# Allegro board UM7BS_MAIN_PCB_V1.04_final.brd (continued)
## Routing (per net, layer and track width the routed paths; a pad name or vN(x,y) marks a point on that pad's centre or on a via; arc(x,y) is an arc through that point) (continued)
M_A_DQ7: length 54.6
  TOP w0.102: v1(189.5,78.42) 188.48,77.4 188.48,75.82 188.25,75.58 188.25,75.26 188.33,75.18 188.33,74.92 188.04,74.62 U1.AP51
  TOP w0.127: CN1.18 218.42,96.25 v1(217.82,95.65)
  BOTTOM w0.127: v1(217.82,95.65) 217.01,95.65 216.63,95.26 216.63,93.59 217.31,92.9 217.31,89.89 217.15,89.73 216.91,89.73 216.74,89.89 216.74,92.26 216.61,92.39 216.42,92.39 216.29,92.26 216.29,89.99 216.15,89.85 212.82,89.85 212.62,89.65 212.62,86.93 211.73,86.04 194.9,86.04 191.49,82.63 191.49,81.5 189.5,79.51 v1(189.5,78.42)
M_A_DQ8: length 48.8
  TOP w0.114: v1(188.52,72.9) 188.35,73.07 U1.AP48
  TOP w0.127: v1(217.06,94.45) 217.66,95.05 CN1.22
  LAY4 w0.127: v1(217.06,94.45) 217.06,94.93 215.66,96.33 210.08,96.33 203.47,89.73 198.01,89.73 186.78,78.5 186.78,75.43 187.37,74.84 187.37,73.95 188.42,72.9 v1(188.52,72.9)
M_A_DQ9: length 50.5
  TOP w0.102: U1.AT47 v1(189.51,72.36)
  TOP w0.127: CN1.23 v1(213.25,94.75)
  LAY4 w0.102: 188.61,74.95 188.61,74.74 188.87,74.49 188.87,73.73 188.99,73.6 188.99,73.32 189.51,72.8 v1(189.51,72.36)
  LAY4 w0.127: 188.61,74.95 188.61,79.06 198.01,88.46 203.6,88.46 208.3,93.16 209.36,93.16 209.57,93.36 209.57,94.53 209.72,94.68 209.93,94.68 210.08,94.53 210.08,93.31 210.22,93.16 210.43,93.16 210.58,93.31 210.58,94.91 210.73,95.06 210.94,95.06 211.09,94.91 211.09,93.31 211.24,93.16 211.45,93.16 211.6,93.31 211.6,94.9 211.76,95.06 211.99,95.06 212.15,94.9 212.15,93.28 212.28,93.16 212.53,93.16 212.66,93.28 212.66,94.54 212.86,94.75 v1(213.25,94.75)
M_A_DQ10: length 44.6
  TOP w0.102: v1(191.53,72.71) 191.17,73.07 U1.AY48
  TOP w0.127: CN1.33 214.34,91.75 v1(215.54,90.55)
  LAY4 w0.102: v1(191.53,72.71) 191.91,73.09 191.91,74.61
  LAY4 w0.127: 191.91,74.61 191.91,74.87 192.65,75.61 192.65,78.53 195.09,80.96 202.2,80.96 209.06,87.82 212.39,87.82 212.52,87.7 212.52,87.19 212.65,87.06 212.9,87.06 213.03,87.19 213.03,87.7 213.15,87.82 213.41,87.82 213.54,87.7 213.54,87.19 213.66,87.06 213.92,87.06 214.04,87.19 214.04,87.7 214.17,87.82 214.42,87.82 214.55,87.7 214.55,87.19 214.68,87.06 214.93,87.06 215.06,87.19 215.06,87.7 215.19,87.82 215.41,87.82 215.92,88.33 215.92,90.17 v1(215.54,90.55)
M_A_DQ11: length 44.5
  TOP w0.102: v1(190.52,73.98) 190.28,73.74 U1.AV50
  TOP w0.127: CN1.34 218.42,91.45 v1(217.82,92.05)
  LAY4 w0.102: 190.77,75.38 190.52,75.12 v1(190.52,73.98)
  LAY4 w0.127: 190.77,75.38 191.03,75.63 191.03,79.06 196.11,84.14 200.45,84.14 200.58,84.01 200.58,83.12 200.71,83 200.96,83 201.09,83.12 201.09,84.01 201.21,84.14 201.47,84.14 201.59,84.01 201.59,83.12 201.72,83 201.98,83 202.1,83.12 202.1,84.01 202.23,84.14 202.58,84.14 209.82,91.38 217.16,91.38 v1(217.82,92.05)
M_A_DQ12: length 49.8
  TOP w0.114: v1(188.51,72.28) 188.11,72.28 U1.AP47
  TOP w0.127: CN1.24 v1(218.58,94.45)
  LAY4 w0.127: v1(188.51,72.28) 187.09,73.7 187.09,74.36 186.4,75.05 186.4,78.75 197.81,90.16 203.27,90.16 209.82,96.71 215.82,96.71 217.63,94.9 218.13,94.9 v1(218.58,94.45)
M_A_DQ13: length 48.2
  TOP w0.102: v1(189.49,73.6) 189.35,73.74 U1.AT50
  TOP w0.127: v1(214.77,94.75) 214.17,95.35 CN1.21
  LAY4 w0.102: 188.99,75 188.99,74.74 189.12,74.61 189.12,73.97 v1(189.49,73.6)
  LAY4 w0.127: v1(214.77,94.75) 215.84,94.75 216.04,94.54 216.04,93.33 215.87,93.16 215.62,93.16 215.44,93.33 215.44,94.05 215.32,94.17 215.06,94.17 214.94,94.05 214.94,93.43 214.79,93.28 214.58,93.28 214.43,93.43 214.43,94.15 214.28,94.3 214.07,94.3 213.92,94.15 213.92,93.47 213.79,93.35 213.31,93.35 212.66,92.7 208.47,92.7 203.85,88.08 198.19,88.08 188.99,78.88 188.99,75
M_A_DQ14: length 46.5
  TOP w0.102: v1(191.53,73.34) 191.13,73.74 U1.AY50
  TOP w0.127: v1(214.01,90.55) 213.41,91.15 CN1.35
  LAY4 w0.102: v1(191.53,73.34) 191.15,73.73 191.15,74.61 191.66,75.12
  LAY4 w0.127: v1(214.01,90.55) 214.01,90.18 213.81,89.98 212.81,89.98 212.6,89.78 212.6,88.33 212.48,88.2 212.22,88.2 212.1,88.33 212.1,90.47 211.95,90.62 211.74,90.62 211.59,90.47 211.59,88.33 211.46,88.2 211.21,88.2 211.08,88.33 211.08,90.31 210.9,90.49 210.64,90.49 210.46,90.31 210.46,88.46 210.33,88.33 210.06,88.33 209.94,88.46 209.94,88.82 209.79,88.97 209.58,88.97 209.43,88.82 209.43,88.46 209.3,88.33 208.68,88.33 201.85,81.5 194.99,81.5 192.27,78.78 192.27,75.73 191.66,75.12
M_A_DQ15: length 49.3
  TOP w0.102: v1(190.52,71.95) 190.22,71.65 U1.AV45
  TOP w0.127: CN1.36 v1(218.58,90.85)
  LAY4 w0.102: 191.15,75.12 190.9,74.87 190.9,72.33 v1(190.52,71.95)
  LAY4 w0.127: v1(218.58,90.85) 217.11,90.85 216.96,91 210.58,91 201.95,82.36 200.24,82.36 200.11,82.49 200.11,83.28 199.96,83.43 199.75,83.43 199.61,83.28 199.61,82.49 199.48,82.36 199.22,82.36 199.1,82.49 199.1,83.38 198.97,83.5 198.72,83.5 198.59,83.38 198.59,82.49 198.46,82.36 198.21,82.36 198.08,82.49 198.08,83.38 197.95,83.5 197.7,83.5 197.57,83.38 197.57,82.49 197.45,82.36 197.19,82.36 197.07,82.49 197.07,83.38 196.94,83.5 196.68,83.5 196.56,83.38 196.56,82.49 196.43,82.36 195.09,82.36 191.41,78.68 191.41,75.38 191.15,75.12
M_A_DQ16: length 51.4
  TOP w0.114: v1(188.49,68.52) 188.88,68.91 U1.AT40
  TOP w0.127: v1(218.58,89.05) CN1.42
  LAY3 w0.102: 186.71,74.74 186.96,74.49 186.96,70.04 v1(188.49,68.52)
  LAY3 w0.127: 186.71,74.74 186.58,74.87 186.58,78.55 196.99,88.97 208.3,88.97 210.53,91.2 217.08,91.2 218.58,89.69 v1(218.58,89.05)
M_A_DQ17: length 51.3
  TOP w0.102: U1.AP42 188.36,70.23 v1(188.51,70.37)
  TOP w0.127: CN1.41 213.22,89.35 v1(213.25,89.32)
  LAY3 w0.102: 188.1,75.5 187.9,75.3 187.9,70.98 v1(188.51,70.37)
  LAY3 w0.127: v1(213.25,89.32) 213.22,89.35 211.85,89.35 209.06,86.55 208.81,86.55 208.68,86.68 208.68,87.31 208.55,87.44 208.3,87.44 208.17,87.31 208.17,86.68 208.04,86.55 207.79,86.55 207.66,86.68 207.66,87.31 207.54,87.44 207.28,87.44 207.16,87.31 207.16,86.68 207.03,86.55 206.77,86.55 206.65,86.68 206.65,87.31 206.52,87.44 206.27,87.44 206.14,87.31 206.14,86.68 206.01,86.55 205.76,86.55 205.63,86.68 205.63,87.31 205.5,87.44 205.25,87.44 205.12,87.31 205.12,86.68 205,86.55 204.74,86.55 204.62,86.68 204.62,87.31 204.49,87.44 204.23,87.44 204.11,87.31 204.11,86.68 203.98,86.55 203.73,86.55 203.6,86.68 203.6,87.31 203.47,87.44 203.22,87.44 203.09,87.31 203.09,86.68 202.96,86.55 202.71,86.55 202.58,86.68 202.58,87.31 202.46,87.44 202.2,87.44 202.08,87.31 202.08,86.68 201.95,86.55 201.69,86.55 201.57,86.68 201.57,87.04 201.42,87.19 201.21,87.19 201.06,87.04 201.06,86.68 200.93,86.55 196.36,86.55 188.37,78.56 188.37,75.77 188.1,75.5
M_A_DQ18: length 45.1
  TOP w0.114: U1.AT38 188.93,67.94 v1(189.5,68.52)
  TOP w0.127: CN1.51 v1(213.25,86.35)
  LAY3 w0.102: 190.47,74.81 190.14,74.47 190.14,70.93 190.01,70.8 190.01,69.03 v1(189.5,68.52)
  LAY3 w0.127: v1(213.25,86.35) 213.46,86.35 213.63,86.17 213.63,85.79 213.5,85.66 211.47,85.66 209.95,84.14 209.95,82.23 209.82,82.11 209.22,82.11 209.1,82.23 209.1,82.74 208.97,82.87 208.72,82.87 208.59,82.74 208.59,82.23 208.46,82.11 208.21,82.11 208.08,82.23 208.08,82.74 207.95,82.87 207.7,82.87 207.57,82.74 207.57,82.23 207.45,82.11 207.19,82.11 207.06,82.23 207.06,82.74 206.94,82.87 206.68,82.87 206.56,82.74 206.56,82.23 206.43,82.11 206.18,82.11 206.05,82.23 206.05,82.74 205.92,82.87 205.67,82.87 205.54,82.74 205.54,82.23 205.41,82.11 195.22,82.11 191.25,78.15 191.25,75.59 190.47,74.81
M_A_DQ19: length 48.5
  TOP w0.102: U1.AP40 188.14,68.8 v1(188.49,69.15)
  TOP w0.127: CN1.40 v1(217.82,89.65)
  LAY3 w0.102: v1(188.49,69.15) 187.22,70.42 187.22,74.87 187.09,75
  LAY3 w0.127: v1(217.82,89.65) 217.35,90.12 210.55,90.12 208.69,88.25 196.92,88.25 186.96,78.3 186.96,75.12 187.09,75
M_A_DQ20: length 51.6
  TOP w0.114: U1.AT44 189.31,70.94 v1(189.51,71.13)
  TOP w0.127: CN1.50 v1(218.58,86.65)
  LAY3 w0.102: v1(189.51,71.13) 189.93,71.56 189.93,74.82 190.27,75.16
  LAY3 w0.127: 190.27,75.16 190.87,75.76 190.87,78.4 195.72,83.25 196.23,83.25 196.35,83.12 196.35,82.62 196.48,82.49 196.74,82.49 196.86,82.62 196.86,83.12 196.99,83.25 197.24,83.25 197.37,83.12 197.37,82.62 197.5,82.49 197.75,82.49 197.88,82.62 197.88,83.12 198.01,83.25 198.26,83.25 198.39,83.12 198.39,82.62 198.51,82.49 198.77,82.49 198.89,82.62 198.89,83.12 199.02,83.25 199.28,83.25 199.4,83.12 199.4,82.62 199.53,82.49 199.78,82.49 199.91,82.62 199.91,83.12 200.04,83.25 200.29,83.25 200.42,83.12 200.42,82.62 200.55,82.49 200.8,82.49 200.93,82.62 200.93,83.12 201.05,83.25 201.31,83.25 201.43,83.12 201.43,82.62 201.56,82.49 201.82,82.49 201.94,82.62 201.94,83.12 202.07,83.25 202.32,83.25 202.45,83.12 202.45,82.62 202.58,82.49 202.83,82.49 202.96,82.62 202.96,83.12 203.09,83.25 203.34,83.25 203.47,83.12 203.47,82.62 203.59,82.49 203.85,82.49 203.97,82.62 203.97,83.12 204.1,83.25 204.36,83.25 204.48,83.12 204.48,82.89 204.63,82.74 204.84,82.74 204.99,82.89 204.99,83.12 205.12,83.25 208.42,83.25 211.98,86.81 216.77,86.81 216.93,86.65 v1(218.58,86.65)
M_A_DQ21: length 49.9
  TOP w0.114: v1(190.39,69.92) 189.99,69.52 U1.AV41
  TOP w0.127: CN1.52 218.42,86.05 v1(217.82,85.45)
  LAY3 w0.102: 191.44,74.68 191.15,74.39 191.15,71.06 190.77,70.68 190.77,70.29 190.39,69.92 v1(190.39,69.92)
  LAY3 w0.127: v1(217.82,85.45) 217.08,85.45 216.96,85.32 216.96,82.76 216.81,82.62 216.6,82.62 216.45,82.76 216.45,85.22 216.26,85.41 215.98,85.41 215.79,85.22 215.79,82.8 215.6,82.62 215.34,82.62 215.16,82.8 215.16,83.94 214.95,84.14 214.72,84.14 214.52,83.94 214.52,82.23 213.63,81.35 195.85,81.35 192.65,78.15 192.65,75.88 191.44,74.68
M_A_DQ22: length 47.5
  TOP w0.102: v1(188.49,69.79) 188.21,69.51 U1.AP41
  TOP w0.127: CN1.39 214.15,89.95 v1(214.77,89.32)
  LAY3 w0.102: v1(188.49,69.79) 187.6,70.68 187.6,75.12 187.47,75.25
  LAY3 w0.127: v1(214.77,89.32) 214.35,89.74 211.1,89.74 209.19,87.82 200.75,87.82 200.62,87.7 200.62,87.21 200.47,87.06 200.26,87.06 200.11,87.21 200.11,87.7 199.98,87.82 199.73,87.82 199.6,87.7 199.6,87.21 199.45,87.06 199.24,87.06 199.09,87.21 199.09,87.7 198.97,87.82 197.05,87.82 187.34,78.12 187.34,75.38 187.47,75.25
M_A_DQ23: length 51.3
  TOP w0.102: U1.AV42 v1(190.39,70.62)
  TOP w0.127: v1(214.77,86.35) 214.17,85.75 CN1.53
  LAY3 w0.102: v1(190.39,70.62) 190.9,71.13 190.9,74.63 191.11,74.84
  LAY3 w0.127: v1(214.77,86.35) 214.77,84.72 214.57,84.52 212.95,84.52 212.74,84.32 212.74,81.93 212.54,81.73 212.25,81.73 212.12,81.85 212.12,84.88 211.97,85.03 211.76,85.03 211.61,84.88 211.61,81.85 211.49,81.73 211.23,81.73 211.11,81.85 211.11,84.01 210.98,84.14 210.73,84.14 210.6,84.01 210.6,81.85 210.47,81.73 195.6,81.73 192.27,78.4 192.27,76 191.11,74.84
M_A_DQ24: length 36.7
  TOP w0.102: v1(193.06,76.65) 192.93,76.65 192.63,76.34 192.63,75.26 193.06,74.83 U1.BD52
  TOP w0.127: CN1.67 214.34,81.55 v1(215.54,80.35)
  BOTTOM w0.127: v1(215.54,80.35) 215.54,79.31 215.41,79.19 215.19,79.19 215.07,79.3 215.07,79.58 214.96,79.69 214.75,79.69 214.62,79.56 214.62,79.3 214.5,79.19 212.71,79.19 212.59,79.3 212.59,79.81 212.46,79.95 212.27,79.95 212.14,79.81 212.14,79.3 212.02,79.19 211.79,79.19 211.68,79.3 211.68,79.96 211.57,80.08 211.34,80.08 211.22,79.96 211.22,79.3 211.11,79.19 210.88,79.19 210.77,79.3 210.77,79.96 210.65,80.08 210.43,80.08 210.31,79.96 210.31,79.3 210.17,79.16 200.89,79.16 200.36,79.69 196.03,79.69 193.06,76.72 v1(193.06,76.65)
M_A_DQ25: length 38.5
  TOP w0.102: v1(190.47,76.75) 190.09,76.37 190.09,75.15 U1.AV52
  TOP w0.127: CN1.58 218.42,84.25 v1(217.82,83.65)
  BOTTOM w0.127: v1(190.47,76.75) 190.9,77.18 190.9,78.42 191.15,78.68 191.15,79.43 195.86,84.14 207.77,84.14 207.89,84.03 207.89,83.62 208,83.5 208.23,83.5 208.34,83.62 208.34,84.03 208.46,84.14 208.69,84.14 208.8,84.03 208.8,83.62 208.92,83.5 211.98,83.5 212.62,84.14 215.41,84.14 215.79,84.52 217.44,84.52 217.82,84.14 v1(217.82,83.65)
M_A_DQ26: length 37.5
  TOP w0.102: v1(193.06,77.28) 192.68,77.28 192.42,77.03 192.42,75.56 U1.BC53
  TOP w0.127: CN1.69 213.41,80.95 v1(214.01,80.35)
  BOTTOM w0.127: v1(193.06,77.28) 195.85,80.08 201.03,80.08 201.19,79.92 201.19,79.69 201.34,79.54 204.32,79.54 204.44,79.67 204.44,80.34 204.56,80.46 204.79,80.46 204.9,80.34 204.9,79.67 205.02,79.56 205.24,79.56 205.36,79.67 205.36,80.34 205.47,80.46 205.7,80.46 205.82,80.34 205.82,79.67 205.93,79.56 206.16,79.56 206.27,79.67 206.27,80.34 206.39,80.46 206.62,80.46 206.73,80.34 206.73,79.67 206.84,79.56 207.07,79.56 207.19,79.67 207.19,80.34 207.3,80.46 207.53,80.46 207.64,80.34 207.64,79.67 207.76,79.56 207.99,79.56 208.1,79.67 208.1,80.34 208.22,80.46 208.55,80.46 208.68,80.33 208.93,80.33 209.06,80.46 209.36,80.46 209.47,80.34 209.47,79.7 209.61,79.57 209.8,79.57 209.93,79.7 209.93,80.34 210.05,80.46 212.49,80.46 213.07,79.88 213.07,79.69 213.2,79.57 214.08,79.57 214.41,79.9 214.41,80.05 214.12,80.35 v1(214.01,80.35)
M_A_DQ27: length 38.7
  TOP w0.102: U1.AV51 189.98,74.62 189.69,74.92 189.69,75.18 189.88,75.36 189.88,76.82 v1(190.47,77.41)
  TOP w0.127: CN1.56 v1(218.58,84.85)
  BOTTOM w0.127: v1(190.47,77.41) 190.01,77.87 190.01,78.55 190.39,78.93 190.39,79.74 195.68,85.03 212.23,85.03 213,85.79 216.89,85.79 217.83,84.85 v1(218.58,84.85)
M_A_DQ28: length 38.6
  TOP w0.102: U1.AW51 190.47,74.97 190.75,75.25 190.75,75.82 190.85,75.91 190.85,77.66 v1(190.47,78.04)
  TOP w0.127: CN1.57 213.41,84.55 v1(214.01,85.15)
  BOTTOM w0.127: v1(214.01,85.15) 214.83,85.15 215.03,84.94 215.03,84.65 214.9,84.52 211.83,84.52 211.72,84.41 211.72,84 211.61,83.89 211.38,83.89 211.26,84 211.26,84.41 211.15,84.52 210.92,84.52 210.81,84.41 210.81,84 210.69,83.89 210.46,83.89 210.35,84 210.35,84.41 210.23,84.52 210.01,84.52 209.89,84.41 209.89,84 209.78,83.89 209.55,83.89 209.43,84 209.43,84.41 209.32,84.52 195.71,84.52 190.77,79.59 190.77,78.68 190.47,78.37 v1(190.47,78.04)
M_A_DQ29: length 37.2
  TOP w0.102: v1(193.06,77.92) 192.68,77.92 192.22,77.46 192.22,75.94 191.94,75.66 191.94,75.22 192.31,74.85 U1.BC52
  TOP w0.127: CN1.70 v1(218.58,80.65)
  BOTTOM w0.127: v1(193.06,77.92) 195.6,80.46 201.19,80.46 201.72,79.92 203.6,79.92 203.72,80.04 203.72,80.72 203.83,80.84 215.99,80.84 216.21,80.62 216.21,79.26 216.41,79.06 216.7,79.06 216.9,79.26 216.9,79.94 217.04,80.08 217.23,80.08 217.36,79.94 217.36,79.39 217.56,79.19 217.87,79.19 218.08,79.39 218.08,80.14 v1(218.58,80.65)
M_A_DQ30: length 36.4
  TOP w0.102: U1.AW53 v1(190.47,76.14)
  TOP w0.127: v1(214.01,83.35) 213.41,83.95 CN1.59
  BOTTOM w0.127: v1(214.01,83.35) 214.01,83.63 213.89,83.76 212.95,83.76 212.74,83.56 212.74,83.25 212.62,83.12 207.43,83.12 207.31,83.24 207.31,83.64 207.2,83.76 206.97,83.76 206.85,83.64 206.85,83.24 206.74,83.12 206.51,83.12 206.4,83.24 206.4,83.64 206.28,83.76 206.05,83.76 205.94,83.64 205.94,83.24 205.83,83.12 205.6,83.12 205.48,83.24 205.48,83.64 205.37,83.76 205.14,83.76 205.03,83.64 205.03,83.24 204.91,83.12 204.68,83.12 204.57,83.24 204.57,83.64 204.45,83.76 204.23,83.76 204.11,83.64 204.11,83.24 204,83.12 203.77,83.12 203.65,83.24 203.65,83.64 203.54,83.76 196.02,83.76 191.53,79.27 191.53,78.68 191.15,78.3 191.15,76.82 v1(190.47,76.14)
M_A_DQ31: length 38.5
  TOP w0.102: U1.BB51 191.74,74.82 191.74,76.04 v1(191.84,76.14)
  TOP w0.127: v1(217.06,80.65) 217.66,81.25 CN1.68
  BOTTOM w0.102: v1(191.84,76.14) 192.67,76.97 192.67,78.07 195.83,81.22
  BOTTOM w0.127: v1(217.06,80.65) 216.49,81.22 203.45,81.22 203.33,81.1 203.33,80.72 203.2,80.58 203.01,80.58 202.87,80.72 202.87,81.1 202.76,81.22 202.53,81.22 202.42,81.1 202.42,80.51 202.29,80.38 202.09,80.38 201.96,80.51 201.96,81.1 201.85,81.22 201.62,81.22 201.5,81.1 201.5,80.95 201.39,80.84 201.16,80.84 201.05,80.95 201.05,81.1 200.93,81.22 200.7,81.22 200.59,81.1 200.59,80.95 200.47,80.84 200.25,80.84 200.13,80.95 200.13,81.1 200.02,81.22 199.79,81.22 199.67,81.1 199.67,80.95 199.56,80.84 199.33,80.84 199.22,80.95 199.22,81.1 199.1,81.22 198.87,81.22 198.76,81.1 198.76,80.95 198.65,80.84 198.42,80.84 198.3,80.95 198.3,81.1 198.19,81.22 197.96,81.22 197.85,81.1 197.85,80.95 197.73,80.84 197.5,80.84 197.39,80.95 197.39,81.1 197.27,81.22 197.05,81.22 196.93,81.1 196.93,80.95 196.82,80.84 196.59,80.84 196.47,80.95 196.47,81.1 196.36,81.22 195.83,81.22
M_A_DQ32: length 31.7
  TOP w0.102: v1(197.39,69.15) 197.13,69.42 197,69.55 195.8,69.55 195.66,69.69 195.32,69.69 195.22,69.59 194.99,69.59 194.68,69.9 U1.BG42
  TOP w0.127: v1(213.89,61.15) 213.29,60.55 CN1.129
  BOTTOM w0.102: v1(197.39,69.15) 198,68.55 199.09,68.55 199.15,68.48
  BOTTOM w0.127: v1(213.89,61.15) 214.3,61.56 214.43,61.56 214.6,61.72 214.6,61.95 214.43,62.12 213.82,62.12 213.7,62 213.7,61.78 213.59,61.66 213.36,61.66 213.24,61.78 213.24,62 213.13,62.12 212.76,62.12 212.64,62 212.64,61.27 212.53,61.15 212.3,61.15 212.18,61.27 212.18,62.03 212.05,62.17 211.86,62.17 211.73,62.03 211.73,61.27 211.61,61.15 211.38,61.15 211.27,61.27 211.27,62.88 209.31,64.84 206.14,64.84 202.59,68.38 200.99,68.38 200.9,68.48 199.15,68.48
M_A_DQ33: length 31.4
  TOP w0.102: v1(198.65,69.15) 197.84,69.96 195.97,69.96 195.83,70.1 195.32,70.1 195.03,70.38 U1.BG43
  TOP w0.127: CN1.132 217.66,59.65 v1(217.06,60.25)
  BOTTOM w0.127: v1(217.06,60.25) 217.31,60.5 217.31,61.03 217.19,61.15 216.68,61.15 215.41,62.42 215.41,63.3 215.21,63.5 213.19,63.5 212.74,63.06 212.36,63.06 209.82,65.6 206.52,65.6 202.96,69.15 v1(198.65,69.15)
M_A_DQ34: length 33.6
  TOP w0.102: v1(197.38,66.49) 196.74,67.12 195.37,67.12 195.02,67.47 U1.BG37
  TOP w0.127: v1(214.01,57.55) 213.41,56.95 CN1.141
  BOTTOM w0.102: 200.06,65.97 199.77,66.25 199.02,66.25 198.87,66.11 197.76,66.11 v1(197.38,66.49)
  BOTTOM w0.127: v1(214.01,57.55) 215.11,57.55 215.28,57.37 215.28,57.13 215.11,56.96 212.67,56.96 212.55,57.08 212.55,57.48 212.44,57.6 212.21,57.6 212.1,57.48 212.1,56.71 211.96,56.58 211.77,56.58 211.64,56.71 211.64,57.48 211.53,57.6 211.3,57.6 211.18,57.48 211.18,56.71 211.05,56.58 210.86,56.58 210.73,56.71 210.73,57.48 210.61,57.6 210.38,57.6 210.27,57.48 210.27,57.08 210.15,56.96 209.73,56.96 201.22,65.47 200.55,65.47 200.06,65.97
M_A_DQ35: length 31.9
  TOP w0.102: v1(198.01,66.49) 197.17,67.32 195.62,67.32 U1.BJ37
  TOP w0.127: v1(218.58,57.25) CN1.140
  BOTTOM w0.127: v1(198.01,66.49) 198.52,66.99 200.04,66.99 200.74,66.3 201.5,66.3 209.44,58.36 210.18,58.36 210.3,58.47 210.3,58.88 210.41,58.99 210.64,58.99 210.75,58.88 210.75,58.47 210.87,58.36 211.1,58.36 211.21,58.47 211.21,58.88 211.33,58.99 211.55,58.99 211.67,58.88 211.67,58.47 211.78,58.36 212.01,58.36 212.13,58.47 212.13,58.88 212.24,58.99 212.74,58.99 213.12,58.61 215.54,58.61 216.22,57.93 217.9,57.93 v1(218.58,57.25)
M_A_DQ36: length 29.7
  TOP w0.102: U1.BH42 195.1,69.89 195.75,69.89 195.88,69.76 197.41,69.76 v1(198.01,69.15)
  TOP w0.127: CN1.130 v1(218.58,60.25)
  BOTTOM w0.102: 199.28,68.77 198.4,68.77 v1(198.01,69.15)
  BOTTOM w0.127: v1(218.58,60.25) 217.97,59.63 217.06,59.63 216.3,60.39 216.3,60.9 214.68,62.52 212.27,62.52 209.57,65.22 206.31,65.22 202.76,68.77 199.28,68.77
M_A_DQ37: length 29.8
  TOP w0.114: v1(196.74,69.15) 196.56,69.34 195.55,69.34 U1.BJ41
  TOP w0.127: CN1.131 213.96,59.95 v1(215.16,61.15)
  BOTTOM w0.102: 199.41,68.19 199.1,68.19 198.95,68.34 197.55,68.34 v1(196.74,69.15)
  BOTTOM w0.127: v1(215.16,61.15) 215.58,60.72 215.58,60.43 215.34,60.2 215.06,60.2 214.53,60.72 211.01,60.72 210.77,60.96 210.77,62.74 209.12,64.39 205.95,64.39 202.35,67.99 200.87,67.99 200.67,68.19 199.41,68.19
M_A_DQ38: length 32.2
  TOP w0.102: v1(196.74,66.49) 196.33,66.89 195.18,66.89 U1.BH36
  TOP w0.127: CN1.143 v1(213.25,56.35)
  BOTTOM w0.102: 199.75,65.76 199.64,65.87 197.63,65.87 197.52,65.98 197.25,65.98 v1(196.74,66.49)
  BOTTOM w0.127: 199.75,65.76 200.42,65.09 201.06,65.09 210.01,56.14 210.52,56.14 210.77,55.88 210.77,55.37 210.96,55.18 211.23,55.18 211.44,55.39 211.44,56.09 211.55,56.2 211.78,56.2 211.9,56.09 211.9,55.32 212.03,55.18 212.22,55.18 212.35,55.32 212.35,56.09 212.47,56.2 212.7,56.2 212.81,56.09 212.81,55.26 213.01,55.06 214.44,55.06 214.65,55.26 214.65,56.09 214.39,56.35 v1(213.25,56.35)
M_A_DQ39: length 32.9
  TOP w0.102: U1.BH38 195.29,67.76 195.65,67.76 195.88,67.53 197.6,67.53 v1(198.65,66.49)
  TOP w0.127: CN1.142 217.63,56.65 v1(217.03,57.25)
  BOTTOM w0.127: v1(217.03,57.25) 216.58,57.25 216.43,57.09 216.43,55.75 216.24,55.56 215.98,55.56 215.79,55.75 215.79,57.77 215.59,57.98 209.25,57.98 201.37,65.85 200.68,65.85 200.04,66.49 v1(198.65,66.49)
M_A_DQ40: length 41.7
  TOP w0.102: v1(192.68,67.48) 192.42,67.22 U1.BC36
  TOP w0.127: v1(214.01,55.75) 213.41,55.15 CN1.147
  LAY3 w0.102: v1(192.68,67.48) 193.24,66.92 195.09,66.92 195.31,67.14
  LAY3 w0.127: 195.31,67.14 195.42,67.25 200.42,67.25 208.04,59.63 211.84,59.63 211.97,59.5 211.97,58.36 212.1,58.23 212.35,58.23 212.48,58.36 212.48,59.5 212.61,59.63 215.28,59.63 215.66,59.25 215.66,55.95 215.46,55.75 215.18,55.75 215.05,55.87 215.05,57.96 214.9,58.1 214.69,58.1 214.54,57.96 214.54,55.87 214.41,55.75 v1(214.01,55.75)
M_A_DQ41: length 41
  TOP w0.102: v1(191.91,67.48) 191.91,67.4 191.71,67.2 U1.BA36
  TOP w0.127: CN1.149 214.56,54.55 v1(215.16,53.95)
  LAY3 w0.102: 195.63,66.9 195.42,66.69 192.7,66.69 v1(191.91,67.48)
  LAY3 w0.127: v1(215.16,53.95) 215.16,55.11 214.95,55.31 212.95,55.31 212.74,55.51 212.74,57.6 212.55,57.79 211.54,57.79 211.41,57.91 211.41,59.1 211.26,59.25 211.05,59.25 210.9,59.1 210.9,57.91 210.77,57.79 210.52,57.79 210.39,57.91 210.39,59.12 210.27,59.25 210.01,59.25 209.89,59.12 209.89,57.91 209.76,57.79 209.5,57.79 209.31,57.98 209.31,58.99 209.06,59.25 207.79,59.25 200.14,66.9 195.63,66.9
M_A_DQ42: length 40.9
  TOP w0.114: U1.AU34 189.57,65.61 v1(189.48,65.52)
  TOP w0.127: CN1.157 v1(213.25,52.15)
  LAY3 w0.102: 194.71,64.61 194.3,65.01 189.98,65.01 v1(189.48,65.52)
  LAY3 w0.127: 194.71,64.61 195.8,63.51 200.22,63.51 210.46,53.28 210.46,51.19 210.66,50.99 210.94,50.99 211.14,51.19 211.14,52.01 211.27,52.14 211.52,52.14 211.65,52.01 211.65,50.99 211.77,50.87 215.46,50.87 215.66,51.07 215.66,51.3 215.46,51.5 213.45,51.5 213.25,51.7 v1(213.25,52.15)
M_A_DQ43: length 40.2
  TOP w0.102: U1.AU32 189.57,64.91 v1(189.25,64.58)
  TOP w0.127: CN1.158 v1(218.58,51.85)
  LAY3 w0.102: v1(189.25,64.58) 189.83,64 194.33,64 194.63,63.69
  LAY3 w0.127: 194.63,63.69 195.47,62.85 199.36,62.85 208.83,53.38 208.83,50.46 209.75,49.54 215.87,49.54 217.19,50.87 217.6,50.87 v1(218.58,51.85)
M_A_DQ44: length 40.2
  TOP w0.114: U1.BF36 193.8,67.31 v1(194,67.5)
  TOP w0.127: CN1.146 v1(218.55,55.45)
  LAY3 w0.127: v1(194,67.5) 194.7,67.5 195.95,68.75 200.32,68.75 207.47,61.6 211.22,61.6 212.36,60.45 216.36,60.45 216.55,60.26 216.55,59.62 216.68,59.49 217.19,59.49 217.31,59.36 217.31,59.11 217.19,58.98 216.68,58.98 216.55,58.85 216.55,58.6 216.68,58.47 217.8,58.47 217.95,58.33 217.95,58.11 217.8,57.97 216.68,57.97 216.55,57.84 216.55,56.15 216.76,55.95 217.13,55.95 217.26,56.07 217.26,56.71 217.38,56.83 217.64,56.83 217.76,56.71 217.76,56.07 217.89,55.95 218.05,55.95 v1(218.55,55.45)
M_A_DQ45: length 39.7
  TOP w0.102: U1.BD36 193.13,67.3 v1(193.31,67.48)
  TOP w0.127: CN1.148 217.63,54.85 v1(217.03,55.45)
  LAY3 w0.102: v1(193.31,67.48) 193.67,67.12 194.71,67.12 195.07,67.48
  LAY3 w0.127: 195.07,67.48 195.95,68.37 200.07,68.37 208.42,60.01 208.83,60.01 208.95,60.14 208.95,60.77 209.08,60.9 209.33,60.9 209.46,60.77 209.46,60.14 209.59,60.01 209.84,60.01 209.97,60.14 209.97,60.77 210.1,60.9 210.35,60.9 210.48,60.77 210.48,60.14 210.6,60.01 210.86,60.01 210.99,60.14 210.99,60.5 211.13,60.64 211.34,60.64 211.49,60.5 211.49,60.14 211.62,60.01 215.92,60.01 216.16,59.77 216.16,55.83 216.54,55.45 v1(217.03,55.45)
M_A_DQ46: length 40.5
  TOP w0.102: U1.AV34 190.29,65.8 v1(190.03,65.55)
  TOP w0.127: v1(214.77,52.14) 214.18,51.55 CN1.159
  LAY3 w0.102: 194.81,64.99 194.58,65.22 190.36,65.22 v1(190.03,65.55)
  LAY3 w0.127: 194.81,64.99 195.88,63.92 200.45,63.92 212.24,52.13 212.24,51.4 212.39,51.25 212.6,51.25 212.75,51.4 212.75,52.52 212.88,52.64 216.65,52.64 216.78,52.52 216.78,52.24 216.68,52.14 v1(214.77,52.14)
M_A_DQ47: length 41.7
  TOP w0.102: U1.AV32 190.29,64.86 v1(190.01,64.58)
  TOP w0.127: v1(217.06,51.85) 217.66,51.25 CN1.160
  LAY3 w0.102: 194.76,64.07 194.63,64.2 190.39,64.2 v1(190.01,64.58)
  LAY3 w0.127: v1(217.06,51.85) 217.06,51.63 216.93,51.5 216.3,51.5 216.05,51.26 216.05,50.37 215.61,49.93 212.26,49.93 212.13,50.05 212.13,50.36 212.01,50.48 211.75,50.48 211.63,50.36 211.63,50.05 211.5,49.93 211.25,49.93 211.12,50.05 211.12,50.36 210.99,50.48 210.74,50.48 210.61,50.36 210.61,50.05 210.48,49.93 210,49.93 209.69,50.23 209.69,53.28 199.81,63.16 195.67,63.16 194.76,64.07
M_A_DQ48: length 42.1
  TOP w0.102: v1(193.44,65.6) 193.8,65.96 U1.BF34
  TOP w0.127: CN1.163 v1(213.25,50.35)
  LAY4 w0.127: v1(213.25,50.35) 212.74,49.84 212.74,49.47 212.49,49.21 210.99,49.21 210.84,49.36 210.84,49.57 211.04,49.77 211.79,49.77 211.98,49.97 211.98,50.24 211.79,50.43 210.99,50.43 210.84,50.58 210.84,50.79 210.99,50.94 212.47,50.94 212.62,51.09 212.62,51.3 212.47,51.45 211.11,51.45 210.96,51.6 210.96,51.81 211.11,51.96 212.47,51.96 212.62,52.11 212.62,52.32 212.47,52.46 211.11,52.46 210.96,52.61 210.96,52.82 211.11,52.97 211.45,52.97 211.6,53.12 211.6,53.33 211.45,53.48 210.84,53.48 210.71,53.61 210.71,55.31 200.09,65.93 195.34,65.93 195.27,66 193.84,66 v1(193.44,65.6)
M_A_DQ49: length 42.2
  TOP w0.102: v1(192.04,65.6) 192.42,65.98 U1.BC34
  TOP w0.127: CN1.166 217.66,49.45 v1(217.06,50.05)
  LAY4 w0.127: v1(217.06,50.05) 217.06,49.42 216.86,49.21 216.43,49.21 216.22,49.42 216.22,53.61 215.28,54.55 214.86,54.55 214.73,54.68 214.73,55.06 214.6,55.18 214.35,55.18 214.22,55.06 214.22,54.68 214.1,54.55 213.84,54.55 213.72,54.68 213.72,55.06 213.59,55.18 213.33,55.18 213.21,55.06 213.21,54.68 213.08,54.55 212.87,54.55 199.92,67.5 195.34,67.5 194.53,66.69 193.13,66.69 v1(192.04,65.6)
M_A_DQ50: length 41.5
  TOP w0.102: U1.BA32 191.41,64.74 v1(191.41,64.58)
  TOP w0.127: v1(217.06,47.05) 217.66,46.45 CN1.176
  LAY4 w0.102: v1(191.41,64.58) 191.53,64.58 192.17,63.95 194.58,63.95
  LAY4 w0.127: 194.58,63.95 195.09,63.95 195.67,63.36 199.86,63.36 207.15,56.07 207.15,54.1 207.28,53.98 207.54,53.98 207.66,53.85 207.66,53.6 207.54,53.47 207.28,53.47 207.15,53.34 207.15,49.06 208.75,47.46 216.64,47.46 v1(217.06,47.05)
M_A_DQ51: length 43.3
  TOP w0.102: v1(193.57,63.57) 193.13,64 U1.BD30
  TOP w0.127: v1(213.25,46.15) CN1.177
  LAY4 w0.127: v1(213.25,46.15) 212.53,46.15 211.98,46.7 208.02,46.7 206.33,48.39 206.33,49.2 206.2,49.33 205.5,49.33 205.38,49.46 205.38,49.71 205.5,49.84 206.2,49.84 206.33,49.96 206.33,50.22 206.2,50.34 205.4,50.34 205.25,50.49 205.25,50.7 205.4,50.85 206.2,50.85 206.33,50.98 206.33,51.23 206.2,51.36 205.4,51.36 205.25,51.51 205.25,51.72 205.4,51.87 206.2,51.87 206.33,52 206.33,52.25 206.2,52.38 205.5,52.38 205.38,52.5 205.38,52.76 205.5,52.88 206.2,52.88 206.33,53.01 206.33,53.27 206.2,53.39 205.5,53.39 205.38,53.52 205.38,53.77 205.5,53.9 206.2,53.9 206.33,54.03 206.33,54.28 206.2,54.41 205.5,54.41 205.38,54.54 205.38,54.79 205.5,54.92 206.2,54.92 206.33,55.04 206.33,55.5 199.13,62.7 195.32,62.7 194.96,63.06 194.07,63.06 v1(193.57,63.57)
M_A_DQ52: length 42.4
  TOP w0.102: v1(192.68,65.6) 193.1,66.02 U1.BD34
  TOP w0.127: CN1.165 214.17,49.75 v1(214.77,50.35)
  LAY4 w0.127: v1(192.68,65.6) 193.43,66.35 194.95,66.35 195.65,67.05 199.74,67.05 212.74,54.04 212.74,53.15 213,52.9 215.54,52.9 215.79,52.64 215.79,51.88 215.59,51.68 213.2,51.68 213,51.48 213,51.22 213.2,51.02 215.59,51.02 215.79,50.81 215.79,50.48 215.65,50.35 v1(214.77,50.35)
M_A_DQ53: length 39.5
  TOP w0.102: v1(191.28,65.6) 191.7,66.02 U1.BA34
  TOP w0.127: CN1.164 v1(218.58,50.05)
  LAY4 w0.127: v1(218.58,50.05) 217.89,50.74 217.44,50.74 216.6,51.58 216.6,53.86 213.63,56.83 211.22,56.83 199.53,68.52 195.6,68.52 194.15,67.07 192.75,67.07 v1(191.28,65.6)
M_A_DQ54: length 43.9
  TOP w0.102: v1(194.2,63.57) 193.8,63.96 U1.BF30
  TOP w0.127: CN1.174 v1(218.58,47.05)
  LAY4 w0.127: v1(218.58,47.05) 217.81,46.27 217.41,46.27 217.28,46.14 217.28,44.9 217.16,44.77 216.9,44.77 216.78,44.9 216.78,46.27 216.63,46.42 216.42,46.42 216.27,46.27 216.27,44.9 216.14,44.77 215.89,44.77 215.76,44.9 215.76,46.32 215.51,46.57 212.87,46.57 212.36,47.08 208.27,47.08 206.77,48.58 206.77,55.82 199.59,63.01 195.52,63.01 194.96,63.57 v1(194.2,63.57)
M_A_DQ55: length 42.8
  TOP w0.102: v1(192.8,63.57) 193.07,63.3 U1.BD28
  TOP w0.127: v1(214.77,46.15) 214.32,46.6 212.89,46.6 212.74,46.75 CN1.175
  LAY4 w0.127: v1(192.8,63.57) 193.31,63.06 193.69,63.06 194.07,62.68 194.96,62.68 195.85,61.79 199.28,61.79 204.87,56.2 204.87,49.09 207.79,46.17 208.3,46.17 208.42,46.04 208.42,45.53 208.55,45.4 208.85,45.4 208.97,45.53 208.97,46.14 209.12,46.29 209.33,46.29 209.48,46.14 209.48,45.53 209.61,45.4 209.86,45.4 209.99,45.53 209.99,46.14 210.14,46.29 210.35,46.29 210.5,46.14 210.5,45.53 210.62,45.4 210.88,45.4 211.01,45.53 211.01,46.14 211.15,46.29 211.37,46.29 211.51,46.14 211.51,45.53 211.64,45.4 214.65,45.4 214.77,45.53 v1(214.77,46.15)
M_A_DQ56: length 39.1
  TOP w0.102: v1(196.11,65.52) 196.1,65.52 U1.BJ33
  TOP w0.127: CN1.181 v1(213.25,44.95)
  BOTTOM w0.127: v1(196.11,65.52) 196.79,64.84 198.94,64.84 211.14,52.64 214.91,52.64 215.8,51.74 215.8,48.25 215.69,48.13 215.16,48.13 215.03,48 215.03,47.81 215.16,47.68 215.69,47.68 215.8,47.56 215.8,47.33 215.69,47.22 215.04,47.22 214.9,47.09 214.9,46.9 215.04,46.76 215.58,46.76 215.8,46.54 215.8,45.8 215.54,45.53 213.84,45.53 v1(213.25,44.95)
M_A_DQ57: length 40.1
  TOP w0.102: v1(198.65,62.3) 197.41,63.53 196.02,63.53 195.69,63.86 195.32,63.86 195.1,63.64 194.8,63.64 U1.BG29
  TOP w0.127: CN1.194 v1(218.58,41.05)
  BOTTOM w0.127: v1(198.65,62.3) 198.65,62.05 210.33,50.37 210.33,48.59 210.21,48.48 209.47,48.48 209.34,48.34 209.34,48.15 209.47,48.02 210.21,48.02 210.33,47.91 210.33,44.52 212.87,41.98 217.65,41.98 v1(218.58,41.05)
M_A_DQ58: length 38.1
  TOP w0.102: v1(197.38,65.52) 196.79,66.11 195.19,66.11 U1.BH34
  TOP w0.127: v1(217.82,45.85) 218.42,45.25 CN1.180
  BOTTOM w0.127: v1(197.38,65.52) 197.5,65.39 199.49,65.39 211.49,53.4 216.18,53.4 216.64,52.93 216.64,45.69 216.81,45.53 217.51,45.53 v1(217.82,45.85)
M_A_DQ59: length 40.2
  TOP w0.102: U1.BG32 194.66,65.04 194.85,65.23 194.86,65.23 194.97,65.34 195.22,65.34 195.32,65.24 195.83,65.24 195.96,65.11 197.86,65.11 v1(198.65,64.33)
  TOP w0.127: CN1.183 214.17,44.35 v1(214.77,44.95)
  BOTTOM w0.127: v1(214.77,44.95) 214.35,44.52 212.99,44.52 212.7,44.81 212.7,47.66 212.81,47.77 213.5,47.77 213.63,47.91 213.63,48.1 213.5,48.23 212.75,48.23 212.64,48.35 212.64,50.7 212.75,50.81 213.64,50.81 213.76,50.93 213.76,51.16 213.64,51.27 212.73,51.27 212.62,51.38 212.62,51.88 212.24,52.26 210.9,52.26 198.83,64.33 v1(198.65,64.33)
M_A_DQ60: length 41.2
  TOP w0.102: U1.BG28 194.68,63.09 194.98,63.39 195.22,63.39 195.48,63.12 196.55,63.12 v1(197.38,62.3)
  TOP w0.127: v1(214.01,40.83) 213.5,41.35 CN1.193
  BOTTOM w0.127: v1(197.38,62.3) 197.76,61.91 197.76,61.79 208.44,51.1 208.44,49.75 208.33,49.64 208.18,49.64 208.04,49.51 208.04,49.32 208.18,49.18 208.33,49.18 208.44,49.07 208.44,48.84 208.33,48.73 207.9,48.73 207.79,48.61 207.79,48.38 207.9,48.27 208.33,48.27 208.44,48.15 208.44,47.92 208.33,47.81 207.99,47.81 207.79,47.61 207.79,47.26 207.99,47.06 209.29,47.06 209.44,46.9 209.44,46.68 209.29,46.53 207.92,46.53 207.79,46.39 207.79,46.2 207.92,46.07 209.33,46.07 209.44,45.96 209.44,44.01 212.23,41.21 213.63,41.21 v1(214.01,40.83)
M_A_DQ61: length 40.8
  TOP w0.102: v1(198.01,62.3) 196.98,63.33 195.74,63.33 U1.BJ29
  TOP w0.127: CN1.192 217.66,41.65 v1(217.06,41.05)
  BOTTOM w0.127: v1(217.06,41.05) 216.51,41.59 212.49,41.59 209.88,44.2 209.88,47.36 209.68,47.56 209.16,47.56 208.96,47.77 208.96,48.71 209.16,48.91 209.71,48.91 209.82,49.02 209.82,49.25 209.71,49.37 209.07,49.37 208.93,49.5 208.93,49.69 209.07,49.82 209.71,49.82 209.82,49.94 209.82,50.17 209.71,50.28 209.26,50.28 208.93,50.61 208.93,51.22 198.01,62.14 v1(198.01,62.3)
M_A_DQ62: length 41.5
  TOP w0.102: U1.BH28 195.28,62.91 196.13,62.91 v1(196.74,62.3)
  TOP w0.127: CN1.191 214.42,41.95 v1(215.54,40.83)
  BOTTOM w0.127: v1(215.54,40.83) 215.03,40.32 212.49,40.32 208.81,44.01 207.59,44.01 207.41,44.19 207.41,44.45 207.59,44.63 208.85,44.63 208.98,44.76 208.98,44.95 208.85,45.09 207.52,45.09 207.41,45.2 207.41,51.5 196.74,62.17 v1(196.74,62.3)
M_A_DQ63: length 38.6
  TOP w0.102: v1(196.74,65.52) 196.35,65.9 195.4,65.9 195.19,65.69 194.9,65.69 U1.BG33
  TOP w0.127: CN1.182 v1(218.58,44.65)
  BOTTOM w0.127: v1(196.74,65.52) 197.17,65.09 199.25,65.09 211.32,53.02 215.87,53.02 216.25,52.64 216.25,45.19 216.8,44.65 v1(218.58,44.65)
M_A_DQS0: length 53.4
  TOP w0.101: v1(187.85,77.28) 187.77,77.28 187.47,76.98 187.47,76.49 187.07,76.09 U1.AM52
  TOP w0.124: v1(217.82,97.83) 217.82,98.16 217.9,98.24 218.64,98.24 218.83,98.05 CN1.12
  BOTTOM w0.124: v1(187.85,77.28) 187.85,77.08 187.71,76.93 187.51,76.93 187.34,77.1 187.34,80.21 189.09,81.97 189.09,83.31 193.9,88.12 206.37,88.12 207.24,88.99 207.24,89.94 207.41,90.11 207.74,90.11 207.94,89.91 207.94,89.04 208.27,88.71 208.98,88.71 209.27,89 209.27,92.42 211.63,94.79 211.63,96.43 212.87,97.66 216.7,97.66 217.3,98.26 217.67,98.26 217.82,98.11 v1(217.82,97.83)
M_A_DQS1: length 47.7
  TOP w0.124: v1(190.52,72.71) 190.17,72.36 U1.AV47 ; CN1.29 213,92.95 213.15,93.1 214.07,93.1 214.18,92.98 214.18,92.82 v1(214.01,92.65)
  LAY4 w0.101: 190.02,79.16 189.88,79.02 189.88,73.19 190.14,72.94 190.29,72.94 v1(190.52,72.71)
  LAY4 w0.112: v1(214.01,92.65) 214.24,92.42 214.24,92.26 214.12,92.14 208.85,92.14 203.8,87.1 203.48,87.1 203.19,86.8 203.19,85.86 203.04,85.7 202.68,85.7 202.49,85.89 202.49,86.84 202.15,87.18 201.69,87.18 201.35,86.84 201.35,85.92 201.13,85.7 200.83,85.7 200.61,85.92 200.61,86.84 200.26,87.2 199.83,87.2 199.47,86.84 199.47,86.04 199.25,85.83 198.9,85.83 198.74,85.99 198.74,86.84 198.52,87.06 197.98,87.06 197.52,86.6 197.52,85.76 197.41,85.65 196.51,85.65 190.02,79.16
M_A_DQS2: length 52.3
  TOP w0.124: U1.AT42 189.29,70.51 v1(189.52,70.51) ; CN1.47 213,87.55 213.08,87.63 214.26,87.63 214.56,87.94 214.56,88.38 v1(214.65,88.46)
  LAY3 w0.101: v1(189.52,70.51) 189.52,70.34 189.45,70.27 189.21,70.27 189.11,70.37 189.11,74.73 190.09,75.71 190.09,78.54 190.57,79.03
  LAY3 w0.112: v1(214.65,88.46) 214.47,88.28 214.47,88 214.11,87.64 212.01,87.64 208.35,83.98 205.55,83.98 205.21,84.32 205.21,85.12 205.03,85.3 204.73,85.3 204.51,85.08 204.51,84.13 204.19,83.81 203.69,83.81 203.33,84.17 203.33,85.12 203.15,85.3 202.85,85.3 202.63,85.08 202.63,84.33 202.35,84.05 201.77,84.05 201.45,84.37 201.45,85.12 201.27,85.3 200.97,85.3 200.75,85.08 200.75,84.36 200.5,84.11 199.84,84.11 199.57,84.37 199.57,85.12 199.39,85.3 199.09,85.3 198.87,85.08 198.87,84.33 198.55,84.01 198.05,84.01 197.69,84.37 197.69,85.12 197.51,85.3 197.21,85.3 197.03,85.12 197.03,84.32 196.72,84.01 195.56,84.01 190.57,79.03
M_A_DQS3: length 38.1
  TOP w0.101: v1(191.84,77.92) 191.6,77.68 191.34,77.68 191.05,77.39 191.05,75.79 190.96,75.69 U1.AY52
  TOP w0.124: CN1.64 218.83,82.45 218.65,82.63 217.71,82.63 217.6,82.52 217.6,82.06 v1(217.82,81.85)
  BOTTOM w0.101: v1(191.84,77.92) 192.05,77.7 192.17,77.7 192.24,77.78 192.24,78.77 192.45,78.97
  BOTTOM w0.124: 192.45,78.97 195.49,82.02 195.78,82.02 215.45,82.02 215.64,82.21 215.64,83.54 215.96,83.86 216.81,83.86 217.15,83.52 217.15,83 217.6,82.55 217.6,82.07 v1(217.82,81.85)
M_A_DQS4: length 31
  TOP w0.101: U1.BH40 195.1,68.92 195.75,68.92 196.11,68.57 196.83,68.57 197.08,68.32 197.08,68.25 v1(197.38,67.96)
  TOP w0.124: CN1.137 212.93,58.15 213.06,58.28 214.24,58.28 214.47,58.51 214.47,59.07 v1(214.52,59.12)
  BOTTOM w0.124: v1(197.38,67.96) 197.38,67.68 197.55,67.5 200.26,67.5 200.71,67.05 201.9,67.05 206.28,62.67 207.37,62.67 207.67,62.36 207.67,61.28 207.84,61.11 208.28,61.11 208.41,61.23 208.41,62.4 208.7,62.69 209.27,62.69 209.57,62.39 209.57,60.52 210.28,59.81 214.08,59.81 214.34,59.55 214.34,59.3 v1(214.52,59.12)
M_A_DQS5: length 38.9
  TOP w0.124: CN1.154 218.84,53.05 218.63,53.25 218.31,53.25 v1(218.08,53.02) ; v1(188.49,64.58) 188.86,64.96 U1.AT32
  LAY3 w0.112: v1(218.08,53.02) 217.79,53.31 215.66,53.31 215.59,53.23 212,53.23 200.4,64.84 195.82,64.84 194.64,66.01 189.25,66.01 189.09,65.85 189.09,65.14 188.84,64.89 188.58,64.89 188.49,64.8 v1(188.49,64.58)
M_A_DQS6: length 41.4
  TOP w0.124: v1(192.8,64.58) 192.42,64.2 U1.BC30 ; v1(214.65,49.12) 214.65,48.38 214.37,48.1 213.08,48.1 212.93,47.95 CN1.171
  LAY4 w0.101: v1(192.8,64.58) 193.24,65.01 194.75,65.01 194.88,64.89
  LAY4 w0.112: 194.88,64.89 199.96,64.89 209.84,55.01 209.84,54.39 209.71,54.27 209.35,54.27 208.98,53.91 208.98,53.41 209.31,53.09 209.82,53.09 210.04,52.87 210.04,52.57 209.86,52.39 209.47,52.39 209.11,52.03 209.11,51.53 209.43,51.21 209.82,51.21 210.04,50.99 210.04,50.69 209.86,50.51 209.47,50.51 209.11,50.15 209.11,48.91 209.65,48.37 214.27,48.37 214.52,48.62 214.52,49 v1(214.65,49.12)
M_A_DQS7: length 39.5
  TOP w0.101: U1.BH32 195.1,65.03 195.73,65.03 195.85,64.91 196.46,64.91 196.64,64.73 196.97,64.73 v1(197.38,64.33)
  TOP w0.124: CN1.188 218.84,42.85 218.63,43.05 217.71,43.05 217.36,43.4 217.36,43.74 v1(217.06,44.05)
  BOTTOM w0.124: v1(197.38,64.33) 197.18,64.13 197.18,63.94 197.82,63.3 198.56,63.3 211.16,50.7 211.16,44.95 212.83,43.28 217.18,43.28 217.35,43.45 217.35,43.76 v1(217.06,44.05)
M_A_DQS#0: length 53.5
  TOP w0.101: v1(187.85,76.57) 187.27,75.99 187.27,75.27 187.36,75.18 187.36,74.92 187.07,74.62 U1.AM51
  TOP w0.124: CN1.10 218.76,98.65 218.61,98.49 217.98,98.49 v1(217.82,98.65)
  BOTTOM w0.124: v1(187.85,76.57) 187.74,76.68 187.4,76.68 187.09,76.99 187.09,80.32 188.84,82.07 188.84,83.41 193.8,88.37 206.27,88.37 206.99,89.09 206.99,90.05 207.3,90.36 207.84,90.36 208.19,90.01 208.19,89.15 208.38,88.96 208.88,88.96 209.02,89.1 209.02,92.53 211.38,94.89 211.38,96.53 212.76,97.91 216.6,97.91 217.2,98.51 217.69,98.51 v1(217.82,98.65)
M_A_DQS#1: length 47.8
  TOP w0.124: U1.AV48 190.24,73.07 v1(190.52,73.34) ; v1(214.65,92.65) 214.44,92.86 214.44,93.09 214.18,93.35 213.06,93.35 212.87,93.55 CN1.27
  LAY4 w0.101: v1(190.52,73.34) 190.31,73.14 190.22,73.14 190.09,73.28 190.09,78.88 190.19,78.99
  LAY4 w0.112: 190.19,78.99 196.61,85.41 197.5,85.41 197.76,85.66 197.76,86.5 198.08,86.82 198.42,86.82 198.5,86.74 198.5,85.89 198.8,85.59 199.35,85.59 199.71,85.95 199.71,86.74 199.93,86.96 200.16,86.96 200.38,86.74 200.38,85.82 200.73,85.46 201.23,85.46 201.59,85.82 201.59,86.74 201.79,86.95 202.05,86.95 202.25,86.74 202.25,85.79 202.59,85.46 203.14,85.46 203.43,85.76 203.43,86.71 203.58,86.86 203.9,86.86 208.95,91.9 214.22,91.9 214.48,92.16 214.48,92.48 v1(214.65,92.65)
M_A_DQS#2: length 52.2
  TOP w0.124: CN1.45 212.88,88.15 213.14,87.88 214.15,87.88 214.31,88.04 214.31,88.16 v1(214.01,88.46) ; U1.AT41 189.38,69.89 v1(189.5,69.89)
  LAY3 w0.101: v1(189.5,69.89) 189.32,70.07 189.12,70.07 188.9,70.29 188.9,74.81 189.88,75.79 189.88,78.68 190.4,79.19
  LAY3 w0.112: 190.4,79.19 195.46,84.25 196.62,84.25 196.79,84.42 196.79,85.21 197.11,85.54 197.61,85.54 197.93,85.21 197.93,84.47 198.15,84.25 198.45,84.25 198.63,84.43 198.63,85.18 198.99,85.54 199.49,85.54 199.81,85.21 199.81,84.47 199.94,84.35 200.4,84.35 200.51,84.46 200.51,85.18 200.87,85.54 201.37,85.54 201.69,85.21 201.69,84.47 201.87,84.29 202.25,84.29 202.39,84.43 202.39,85.18 202.75,85.54 203.25,85.54 203.57,85.21 203.57,84.27 203.79,84.05 204.09,84.05 204.27,84.23 204.27,85.18 204.63,85.54 205.13,85.54 205.45,85.21 205.45,84.42 205.65,84.22 208.25,84.22 211.91,87.88 214.01,87.88 214.23,88.1 214.23,88.24 v1(214.01,88.46)
M_A_DQS#3: length 38.1
  TOP w0.101: U1.BA51 191.44,74.98 191.16,75.26 191.16,75.59 191.26,75.68 191.26,77.28 191.43,77.46 191.66,77.46 v1(191.84,77.28)
  TOP w0.124: CN1.62 218.83,83.05 218.66,82.88 217.6,82.88 217.35,82.63 217.35,82.01 v1(217.19,81.85)
  BOTTOM w0.101: v1(191.84,77.28) 192.04,77.48 192.26,77.48 192.46,77.69 192.46,78.63 192.63,78.8
  BOTTOM w0.124: 192.63,78.8 195.59,81.77 215.55,81.77 215.9,82.11 215.9,83.44 216.06,83.6 216.71,83.6 216.9,83.41 216.9,82.9 217.35,82.44 217.35,82.01 v1(217.19,81.85)
M_A_DQS#4: length 31
  TOP w0.101: v1(196.74,67.96) 196.87,68.09 196.87,68.23 196.74,68.35 196.02,68.35 195.65,68.72 195.31,68.72 195.03,68.44 U1.BG39
  TOP w0.124: v1(213.89,59.12) 214.22,58.79 214.22,58.62 214.14,58.53 213.14,58.53 212.92,58.75 CN1.135
  BOTTOM w0.124: v1(213.89,59.12) 214.09,59.33 214.09,59.44 213.98,59.56 210.17,59.56 209.32,60.41 209.32,62.29 209.16,62.44 208.81,62.44 208.66,62.29 208.66,61.13 208.39,60.86 207.74,60.86 207.42,61.18 207.42,62.25 207.26,62.41 206.17,62.41 201.79,66.79 200.61,66.79 200.15,67.25 197.45,67.25 v1(196.74,67.96)
M_A_DQS#5: length 38.9
  TOP w0.124: CN1.152 218.84,53.65 218.7,53.51 218.36,53.51 v1(218.08,53.79) ; U1.AT34 188.86,65.85 v1(188.49,65.47)
  LAY3 w0.112: v1(218.08,53.79) 217.83,53.55 215.56,53.55 215.49,53.47 212.1,53.47 200.5,65.07 195.92,65.07 194.74,66.25 189.15,66.25 188.86,65.95 188.86,65.24 188.74,65.13 188.61,65.13 188.49,65.25 v1(188.49,65.47)
M_A_DQS#6: length 41.4
  TOP w0.124: v1(192.17,64.58) 192.42,64.83 U1.BC32 ; CN1.169 212.92,48.55 213.12,48.35 214.27,48.35 214.4,48.48 214.4,48.74 v1(214.01,49.12)
  LAY4 w0.101: v1(192.17,64.58) 192.8,65.22 194.88,65.22 194.97,65.13
  LAY4 w0.112: 194.97,65.13 200.06,65.13 210.08,55.11 210.08,54.29 209.81,54.03 209.45,54.03 209.22,53.81 209.22,53.51 209.4,53.33 209.92,53.33 210.28,52.97 210.28,52.47 209.96,52.15 209.57,52.15 209.35,51.93 209.35,51.63 209.53,51.45 209.92,51.45 210.28,51.09 210.28,50.59 209.96,50.27 209.57,50.27 209.35,50.05 209.35,49.01 209.75,48.61 214.17,48.61 214.28,48.72 214.28,48.85 v1(214.01,49.12)
M_A_DQS#7: length 39.6
  TOP w0.101: v1(196.74,64.33) 196.36,64.71 195.77,64.71 195.65,64.83 195.32,64.83 195.04,64.55 U1.BG31
  TOP w0.124: CN1.186 218.84,43.45 218.7,43.31 217.81,43.31 217.61,43.51 217.61,43.84 v1(217.82,44.05)
  BOTTOM w0.124: v1(217.82,44.05) 217.6,43.82 217.6,43.34 217.29,43.03 212.73,43.03 210.91,44.85 210.91,50.59 198.46,63.05 197.72,63.05 196.92,63.84 196.92,64.14 196.82,64.24 v1(196.74,64.33)
M_A_RAS#: length 37.5
  TOP w0.102: U1.BA40 191.71,68.95 v1(192.17,69.41)
  TOP w0.203: v1(217.82,65.72) 218.34,66.25 CN1.110
  LAY3 w0.102: 196.54,71.26 195.8,71.26 194.33,69.79 192.55,69.79 v1(192.17,69.41)
  LAY3 w0.203: v1(217.82,65.72) 217.7,65.85 213.63,65.85 209.38,70.11 208.54,70.11 208.37,69.93 208.37,69.08 208.19,68.9 207.93,68.9 207.76,69.08 207.76,69.93 207.58,70.11 207.33,70.11 207.15,69.93 207.15,68.7 206.97,68.52 206.72,68.52 206.54,68.7 206.54,69.93 206.36,70.11 206.11,70.11 205.93,69.93 205.93,69.59 205.75,69.41 205.5,69.41 205.32,69.59 205.32,69.93 205.14,70.11 204.8,70.11 203.65,71.26 196.54,71.26
M_A_WE#: length 34.5
  TOP w0.102: v1(198.65,72.33) 197.38,71.06 195.29,71.06 U1.BH44
  TOP w0.203: CN1.113 v1(213.25,65.35)
  LAY4 w0.203: v1(198.65,72.33) 202.2,72.33 204.8,69.73 205.48,69.73 205.66,69.55 205.66,68.32 205.84,68.14 206.09,68.14 206.27,68.32 206.27,69.55 206.45,69.73 206.7,69.73 206.88,69.55 206.88,68.32 207.06,68.14 207.31,68.14 207.49,68.32 207.49,69.55 207.67,69.73 207.92,69.73 208.1,69.55 208.1,68.32 208.28,68.14 208.53,68.14 208.71,68.32 208.71,69.55 208.88,69.73 209.14,69.73 209.32,69.55 209.32,68.32 209.49,68.14 209.75,68.14 209.92,68.32 209.92,69.26 210.08,69.41 210.46,69.41 211.85,68.01 211.85,66.74 v1(213.25,65.35)
M_CKE0: length 34.5
  TOP w0.102: v1(191.63,71.39) 191.84,71.18 U1.BB44
  TOP w0.203: CN1.73 v1(213.25,77.35)
  LAY3 w0.102: v1(191.63,71.39) 191.91,71.67 191.91,74.36 192.8,75.25 193.06,75.25 193.25,75.44
  LAY3 w0.203: 193.25,75.44 193.57,75.76 193.57,77.15 195.85,79.44 200.17,79.44 200.68,78.93 215.03,78.93 215.16,78.81 215.16,78.12 214.95,77.92 213.82,77.92 v1(213.25,77.35)
M_CKE1: length 35.8
  TOP w0.102: U1.AY42 191.01,70.02 v1(191.41,70.42)
  TOP w0.203: v1(218.46,77.05) CN1.74
  LAY3 w0.102: v1(191.41,70.42) 192.14,71.16 192.14,74.26 192.62,74.74 193.06,74.74 193.31,75
  LAY3 w0.203: 193.31,75 194.01,75.69 194.01,76.96 195.47,78.42 210.2,78.42 211.78,76.85 217.14,76.85 217.33,77.05 v1(218.46,77.05)
M_CLK_DDR0: length 38.6
  TOP w0.101: v1(193.44,69.41) 193.13,69.1 U1.BD40
  TOP w0.124: v1(214.01,69.28) 214.26,69.03 214.26,68.87 214.03,68.64 213.23,68.64 212.92,68.95 CN1.101
  BOTTOM w0.124: v1(214.01,69.28) 214.4,68.9 214.4,68.72 214.23,68.55 213.27,68.55 212.62,69.2 212.62,73.14 212.32,73.43 211.42,73.43 211.17,73.18 211.17,72.84 210.91,72.58 205.35,72.58 205.08,72.32 205.08,71.44 204.95,71.31 204.56,71.31 204.38,71.48 204.38,72.36 204.16,72.58 203.44,72.58 203.22,72.36 203.22,71.39 203.1,71.27 202.62,71.27 202.48,71.42 202.48,72.36 202.25,72.58 201.54,72.58 201.28,72.32 201.28,71.42 201.13,71.27 200.7,71.27 200.58,71.4 200.58,72.36 200.35,72.58 199.79,72.58 199.47,72.27 199.47,71.86 199.21,71.6 195.91,71.6 194.4,70.09 193.94,70.09 193.68,69.83 193.68,69.65 v1(193.44,69.41)
M_CLK_DDR1: length 38.6
  TOP w0.101: v1(192.8,68.39) 193.13,68.06 U1.BD38
  TOP w0.124: CN1.102 218.84,68.65 218.72,68.53 218.33,68.53 v1(218.08,68.79)
  BOTTOM w0.114: 194.77,69.12 194.67,69.02 193.23,69.02 192.97,68.77 192.97,68.56 v1(192.8,68.39)
  BOTTOM w0.124: v1(218.08,68.79) 216.72,68.79 215.05,67.12 210.89,67.12 210.44,67.57 210.44,67.97 210.61,68.14 211.35,68.14 211.6,68.39 211.6,69.03 211.33,69.31 210.56,69.31 210.46,69.41 210.46,70.04 210.2,70.3 208.57,70.3 208.31,70.03 208.31,69.37 208.13,69.19 207.83,69.19 207.61,69.41 207.61,70.26 207.36,70.51 206.7,70.51 206.41,70.22 206.41,68.91 206.3,68.81 205.85,68.81 205.71,68.95 205.71,69.92 205.37,70.26 196.91,70.26 196.6,69.95 195.6,69.95 194.77,69.12
M_CLK_DDR#0: length 38.6
  TOP w0.101: U1.BF40 193.8,69.14 v1(194.07,69.41)
  TOP w0.124: CN1.103 212.93,68.35 212.97,68.39 214.13,68.39 214.51,68.77 214.51,69.15 v1(214.65,69.28)
  BOTTOM w0.124: v1(214.65,69.28) 214.65,68.62 214.33,68.3 213.16,68.3 212.36,69.1 212.36,73.04 212.22,73.18 211.52,73.18 211.42,73.08 211.42,72.73 211.02,72.33 205.45,72.33 205.34,72.21 205.34,71.34 205.06,71.06 204.45,71.06 204.13,71.38 204.13,72.25 204.05,72.33 203.55,72.33 203.47,72.25 203.47,71.29 203.2,71.02 202.52,71.02 202.23,71.31 202.23,72.25 202.15,72.33 201.64,72.33 201.53,72.21 201.53,71.31 201.24,71.02 200.6,71.02 200.32,71.29 200.32,72.25 200.24,72.33 199.89,72.33 199.72,72.16 199.72,71.75 199.32,71.35 196.02,71.35 194.5,69.84 194.04,69.84 193.95,69.74 193.95,69.53 v1(194.07,69.41)
M_CLK_DDR#1: length 38.6
  TOP w0.101: U1.BF38 193.8,68.03 v1(193.44,68.39)
  TOP w0.124: v1(218.08,68.02) 218.33,68.28 218.61,68.28 218.84,68.05 CN1.104
  BOTTOM w0.114: v1(193.44,68.39) 193.31,68.39 193.22,68.49 193.22,68.66 193.34,68.78 194.79,68.78 194.94,68.94
  BOTTOM w0.124: v1(218.08,68.02) 217.57,68.54 216.82,68.54 215.16,66.87 210.78,66.87 210.19,67.46 210.19,68.08 210.5,68.39 211.24,68.39 211.35,68.5 211.35,68.93 211.22,69.05 210.45,69.05 210.2,69.3 210.2,69.94 210.1,70.05 208.68,70.05 208.56,69.93 208.56,69.27 208.23,68.94 207.72,68.94 207.36,69.3 207.36,70.15 207.25,70.26 206.8,70.26 206.66,70.12 206.66,68.81 206.41,68.56 205.74,68.56 205.46,68.85 205.46,69.82 205.26,70.01 197.01,70.01 196.7,69.7 195.71,69.7 194.94,68.94
M_CS#0: length 39.7
  TOP w0.102: U1.AY38 190.77,68.17 v1(190.77,68.39)
  TOP w0.203: v1(218.58,65.05) CN1.114
  LAY3 w0.102: v1(190.77,68.39) 191.15,68.77 191.41,68.77 191.66,69.03 194.33,69.03 195.22,69.92 195.22,70.17 195.85,70.8 196.36,70.8 196.49,70.68 196.99,70.68
  LAY3 w0.203: v1(218.58,65.05) 217.61,65.05 217.31,65.34 215.54,65.34 215.03,64.84 212.74,64.84 212.19,65.39 212.19,65.64 212.51,65.96 212.51,66.22 212.33,66.39 212.07,66.39 211.76,66.08 211.5,66.08 211.32,66.25 211.32,66.51 211.64,66.83 211.64,67.08 211.46,67.26 211.21,67.26 210.89,66.94 210.64,66.94 210.46,67.12 210.46,67.37 210.78,67.69 210.78,67.94 210.6,68.12 210.35,68.12 210.03,67.8 209.78,67.8 209.64,67.93 209.64,69.1 209.47,69.28 209.21,69.28 209.04,69.1 209.04,68.09 208.83,67.88 206.27,67.88 203.47,70.68 196.99,70.68
M_CS#1: length 35.9
  TOP w0.102: v1(189.25,67.5) 189.57,67.83 U1.AU38
  TOP w0.203: CN1.121 v1(213.25,62.95)
  LAY4 w0.203: v1(213.25,62.95) 213.25,63.31 213.38,63.44 215.22,63.44 215.41,63.62 215.41,63.89 215.22,64.07 211.22,64.07 209.63,65.66 206.07,65.66 200.73,71.01 194.94,71.01 193.84,69.92 191.03,69.92 190.26,69.15 190.26,68.52 v1(189.25,67.5)
M_ODT0: length 40.9
  TOP w0.178: U1.AV36 190.64,67.33 v1(190.64,67.48)
  TOP w0.203: v1(217.82,63.18) 217.82,63.82 218.45,64.45 CN1.116
  LAY3 w0.102: v1(190.64,67.48) 191.18,68.01 194.33,68.01 195.98,69.66 196.74,69.66
  LAY3 w0.203: v1(217.82,63.18) 217.82,62.63 218.03,62.42 218.64,62.42 218.84,62.63 218.84,63.62 218.64,63.82 216.77,63.82 216.59,63.64 216.59,62.35 216.41,62.17 216.16,62.17 215.98,62.35 215.98,63.64 215.81,63.82 212.23,63.82 209.82,66.23 206.39,66.23 202.96,69.66 196.74,69.66
M_ODT1: length 39.4
  TOP w0.102: v1(191.41,68.39) 191.71,68.09 U1.BA38
  TOP w0.203: v1(217.82,61.91) 217.82,62.17 218.9,63.25 CN1.120
  LAY3 w0.102: 196.99,70.17 196.49,70.17 196.31,69.99 195.8,69.99 194.63,68.82 191.97,68.82 191.53,68.39 v1(191.41,68.39)
  LAY3 w0.203: v1(217.82,61.91) 217.82,61.53 218.03,61.33 219.14,61.33 219.35,61.53 219.35,64.2 219.09,64.45 215.66,64.45 215.54,64.33 212.49,64.33 209.95,66.87 206.52,66.87 203.22,70.17 196.99,70.17
MDI0+: length 14.8
  TOP w0.102: U23.7 106.64,39.06 107.13,39.54 110.1,39.54 111.43,38.22 111.43,37 112.61,35.82 114.32,35.82 v1(114.44,35.7)
  BOTTOM w0.102: U22.1 117.98,36.45 117.53,36.45 116.92,35.85 114.59,35.85 v1(114.44,35.7)
MDI0-: length 14.8
  TOP w0.102: U23.8 106.64,40.33 107.13,39.84 110.23,39.84 111.73,38.34 111.73,37.12 112.73,36.12 114.28,36.12 v1(114.44,36.27)
  BOTTOM w0.102: U22.2 117.98,36.75 117.4,36.75 116.79,36.14 114.57,36.14 v1(114.44,36.27)
MDI1+: length 15.4
  TOP w0.102: v1(116.87,37.56) 116.92,37.5 116.92,37.36 116.86,37.3 116.65,37.3 116.53,37.18 116.53,36.04 115.11,34.62 112.08,34.62 109.34,31.89 107.09,31.89 106.64,31.44 U23.1
  BOTTOM w0.101: U22.4 117.65,37.6 117.63,37.63 116.93,37.63 v1(116.87,37.56)
MDI1-: length 15.4
  TOP w0.102: v1(116.23,37.56) 116.23,36.17 114.99,34.92 111.95,34.92 109.22,32.19 107.16,32.19 106.64,32.71 U23.2
  BOTTOM w0.101: U22.5 117.6,38 117.58,37.98 116.65,37.98 v1(116.23,37.56)
MDI2+: length 17.8
  LAY3 w0.102: v1(116.87,38.89) 116.73,39.02 116.73,39.26 116.36,39.63 112.53,39.63 111.21,38.31 111.21,36.2 111.02,36.01 110.45,36.01 v1(110.17,36.29)
  BOTTOM w0.101: v1(116.87,38.89) 116.92,38.94 117.49,38.94 117.63,38.8 U22.7
  BOTTOM w0.102: v1(110.17,36.29) 109.95,36.08 109.58,36.08 109.19,35.68 109.19,33.72 108.96,33.49 107.13,33.49 106.65,33.97 U24.7
